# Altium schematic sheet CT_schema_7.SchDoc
size 278 x 170 mm
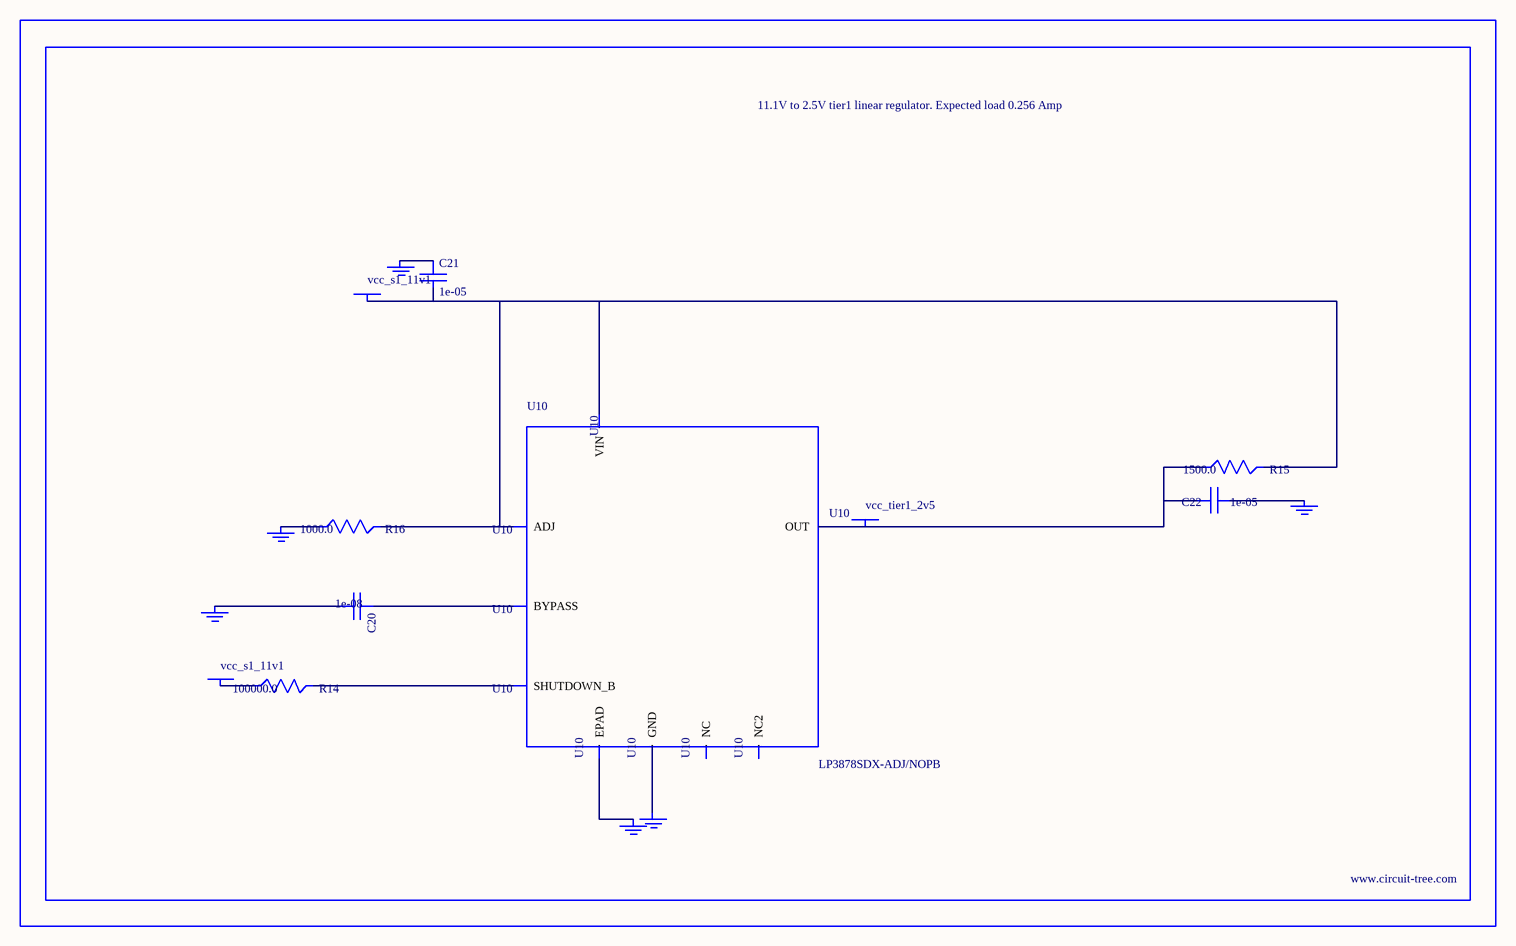
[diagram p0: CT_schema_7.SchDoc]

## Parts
BORDER6  (no value)
C20  1e-08  [C0402]
C21  1e-05  [C1206]
C22  1e-05  [C1210]
GND_INSTANCE_6_0  (no value)
GND_INSTANCE_6_1  (no value)
GND_INSTANCE_6_2  (no value)
GND_INSTANCE_6_3  (no value)
GND_INSTANCE_6_4  (no value)
GND_INSTANCE_6_5  (no value)
POWER_INSTANCE_6_0  vcc_s1_11v1
POWER_INSTANCE_6_1  vcc_s1_11v1
POWER_INSTANCE_6_2  vcc_tier1_2v5
R14  100000.0  [R0603]
R15  1500.0  [R0603]
R16  1000.0  [R0603]
U10  LP3878SDX-ADJ/NOPB  [WSON-8]

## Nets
NetC20_1: C20.1 U10.1(BYPASS)
NetC20_2: C20.2 GND_INSTANCE_6_0.0(GND)
NetC21_1: C21.1 GND_INSTANCE_6_1.0(GND)
NetC21_2: C21.2 POWER_INSTANCE_6_0.0(PWR) R15.2 R16.2 U10.4(VIN) U10.6(ADJ)
NetC22_1: C22.1 GND_INSTANCE_6_2.0(GND)
NetC22_2: C22.2 POWER_INSTANCE_6_2.0(PWR) R15.1 U10.5(OUT)
NetGND_INSTANCE_6_3_0: GND_INSTANCE_6_3.0(GND) R16.1
NetGND_INSTANCE_6_4_0: GND_INSTANCE_6_4.0(GND) U10.PAD(EPAD)
NetGND_INSTANCE_6_5_0: GND_INSTANCE_6_5.0(GND) U10.3(GND)
NetPOWER_INSTANCE_6_1_0: POWER_INSTANCE_6_1.0(PWR) R14.1
NetR14_2: R14.2 U10.8(SHUTDOWN_B)

Not connected (* = marked no-connect by the designer): U10 2(NC) 7(NC2)

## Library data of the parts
BORDER6 = BORDER_PAGE6
C20 = C0402C103K3RAC
C21 = C1206C106K3RACTU
C22 = GRM32DR61E106MA12L
GND_INSTANCE_6_0-GND_INSTANCE_6_5 = GND
POWER_INSTANCE_6_0-POWER_INSTANCE_6_2 = PWR
R14 = RC0603JR-07100KL
R15 = RC0603JR-071K5L
R16 = RC0603JR-071KL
